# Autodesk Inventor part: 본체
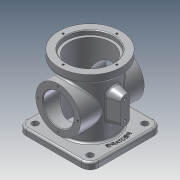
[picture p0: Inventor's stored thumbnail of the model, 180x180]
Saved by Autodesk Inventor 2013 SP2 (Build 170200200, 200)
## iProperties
Created: 2021-03
Part Number: 본체
Material: 알루미늄 6061
Document SubType Name: Modeling
Designer: kumcom8
Density: 2.71 g/cm^3
Mass: 833.811 g
Surface Area: 863.886 cm^2
Volume: 307.679 cm^3
Author: kumcom8
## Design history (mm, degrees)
sketch "스케치1"
  geometry: C1 r 38 at (0, 0); 1 further point
  constraints: 1 centre point, 1 coincident
  dimensions: "d0" = 76 diameter of C1
extrude "돌출1" new body sketch "스케치1" distance "d1" = 111; taper "d2" = 0 deg
sketch "스케치2"
  geometry: C1 r 38 at (0, 0) reference; C2 r 49 at (0, 0)
  constraints: 1 centre point, 1 coincident
  dimensions: "d3" = 98 diameter of C2
extrude "돌출2" join sketch "스케치2" distance "d4" = 13; taper "d5" = 0 deg
sketch "스케치3"
  geometry: L1 (-57, 57)-(57, 57); L2 (57, 57)-(57, -57); L3 (57, -57)-(-57, -57); L4 (-57, -57)-(-57, 57); L5 (-57, 57)-(57, -57); L6 (57, 57)-(-57, -57); C1 r 38 at (0, 0) reference
  constraints: 12 end point, 2 midpoint, 2 parallel, 1 horizontal, 1 perpendicular
  dimensions: "d6" = 114 distance of L2.end L3.end; "d7" = 114 distance of L1.end L2.end
extrude "돌출3" join sketch "스케치3" distance "d8" = 10; taper "d9" = 0 deg
sketch "스케치4"
  geometry: L1 (0, 57)-(0, -57) reference; L2 (0, 0)-(54, 0); C1 r 35 at (54, 0)
  constraints: 2 end point, 1 centre point, 1 coincident, 1 perpendicular
  dimensions: "d10" = 54 distance of L2.start L2.end; "d11" = 70 diameter of C1
extrude "돌출4" join sketch "스케치4" stored distance "d12" = 100; taper "d13" = 0 deg
sketch "스케치5"
  geometry: C1 r 35 at (0, 0) reference; C2 r 24 at (0, 0); 1 further point
  constraints: 1 centre point, 1 coincident
  dimensions: "d14" = 48 diameter of C2
extrude "돌출5" cut sketch "스케치5" stored distance "d15" = 100; taper "d16" = 0 deg
sketch "스케치6"
  geometry: C1 r 49 at (0, 0) reference; C2 r 37 at (0, 0)
  constraints: 1 centre point, 1 coincident
  dimensions: "d17" = 74 diameter of C2
extrude "돌출6" cut sketch "스케치6" distance "d18" = 7; taper "d19" = 0 deg
sketch "스케치7"
  geometry: C1 r 37 at (0, 0) reference; C2 r 33 at (0, 0)
  constraints: 1 centre point, 1 coincident
  dimensions: "d20" = 66 diameter of C2
extrude "돌출7" cut sketch "스케치7" stored distance "d21" = 7; taper "d22" = 0 deg
fillet "모깎기1" dims "d23" = 14
sketch "스케치8"
  geometry: L1 (0, 0)-(0, 42); C1 r 49 at (0, 0) reference; 1 further point
  constraints: 2 end point, 1 coincident, 1 vertical
  dimensions: "d24" = 42 distance of L1.start L1.end
hole "구멍1" sketch "스케치8" at (0, 42) diameter "d25" = 3.242; stored, may be unused: countersink angle "d29" = 90 deg, drill point angle "d31" = 118 deg; dims "d26" = 6, "d27" = 4, "d28" = 2, "d30" = 8
sketch "스케치9"
  geometry: L1 (0, 0)-(0, 31); C1 r 35 at (0, 0) reference; 2 further points
  constraints: 2 end point, 1 coincident, 1 vertical
  dimensions: "d35" = 31 distance of L1.start L1.end
hole "구멍2" sketch "스케치9" at (0, 31) diameter "d36" = 3.242; stored, may be unused: countersink angle "d40" = 90 deg, drill point angle "d42" = 118 deg; dims "d37" = 6, "d38" = 4, "d39" = 2, "d41" = 8
sketch "스케치10"
  geometry: C1 r 5 at (-43, 43); C2 r 5 at (43, 43); C3 r 5 at (-43, -43); C4 r 5 at (43, -43); A1 r 14 centre (43, 43) between (57, 43) and (43, 57) reference; A2 r 14 centre (-43, 43) between (-43, 57) and (-57, 43) reference; A3 r 14 centre (-43, -43) between (-57, -43) and (-43, -57) reference; A4 r 14 centre (43, -43) between (43, -57) and (57, -43) reference
  constraints: 4 centre point, 4 coincident
  dimensions: "d46" = 10 diameter of C1; "d47" = 10 diameter of C2; "d48" = 10 diameter of C3; "d49" = 10 diameter of C4
extrude "돌출8" cut sketch "스케치10" stored distance "d50" = 7; taper "d51" = 0 deg
node "작업 평면2"
sketch "스케치14"
  geometry: L1 (-50, 89)-(-50, 19) reference; L2 (50, 19)-(50, 89) reference; L3 (-50, 54)-(50, 54); L4 (0, 77)-(0, 77); L5 (7, 70)-(7, 41); L6 (0, 34)-(0, 34); L7 (-7, 41)-(-7, 70); A1 r 7 centre (0, 70) between (7, 70) and (0, 77); A2 r 7 centre (0, 70) between (0, 77) and (-7, 70); A3 r 7 centre (0, 41) between (-7, 41) and (0, 34); A4 r 7 centre (0, 41) between (0, 34) and (7, 41); 6 further points
  constraints: 10 end point, 8 point on circle, 8 tangent, 6 point on line, 4 centre point, 4 midpoint, 3 equal radius, 2 parallel, 1 horizontal, 1 perpendicular, 1 vertical alignment
  dimensions: "d57" = 14 distance of point (7, 34) point (-7, 34); "d58" = 43 distance of point (7, 77) point (7, 34); "d59" = 20 distance of point (0, 54) point (0, 34); "d60" = 7 radius of A1
extrude "돌출9" join sketch "스케치14" stored distance "d61" = 7; taper "d62" = 15 deg
sketch "스케치15"
  geometry: A1 r 7 centre (0, 70) between (7, 70) and (-7, 70) reference; A2 r 7 centre (0, 41) between (-7, 41) and (7, 41) reference; 3 further points
  constraints: 2 coincident
hole "구멍3" sketch "스케치15" at (0, 70), (0, 41) diameter "d63" = 4.134; stored, may be unused: countersink angle "d67" = 90 deg, drill point angle "d69" = 118 deg; dims "d64" = 8, "d65" = 4, "d66" = 2, "d68" = 10
sketch "스케치16"
  geometry: C1 r 38 at (0, 0) reference; C2 r 50 at (0, 0)
  constraints: 1 centre point, 1 coincident, 1 other
  dimensions: "d70" = 100 diameter of C2
feature "엠보싱1" sketch "스케치16" dims "d71" = 0.5, "d72" = 0
chamfer "모따기1" distance "d73" = 1; stored, may be unused: second distance "d74" = 2, angle "d75" = 45 deg
fillet "모깎기2" dims "d76" = 3
fillet "모깎기3" dims "d77" = 3
fillet "모깎기4" dims "d78" = 3
fillet "모깎기5" dims "d79" = 3
fillet "모깎기6" dims "d80" = 3
node "솔리드1"
pattern_circular "원형 패턴1" dims angle "d33" = 360 deg
pattern_circular "원형 패턴2" dims angle "d44" = 360 deg
mirror "대칭1"
other parameters: "d56" = 55
